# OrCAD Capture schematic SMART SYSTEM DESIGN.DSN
size A4; title: Smart System design; rev: H MB; company: University Of South Eastern Norway; note: Hugo MASSON-BENOIT; note: Hasbergs Vei 3
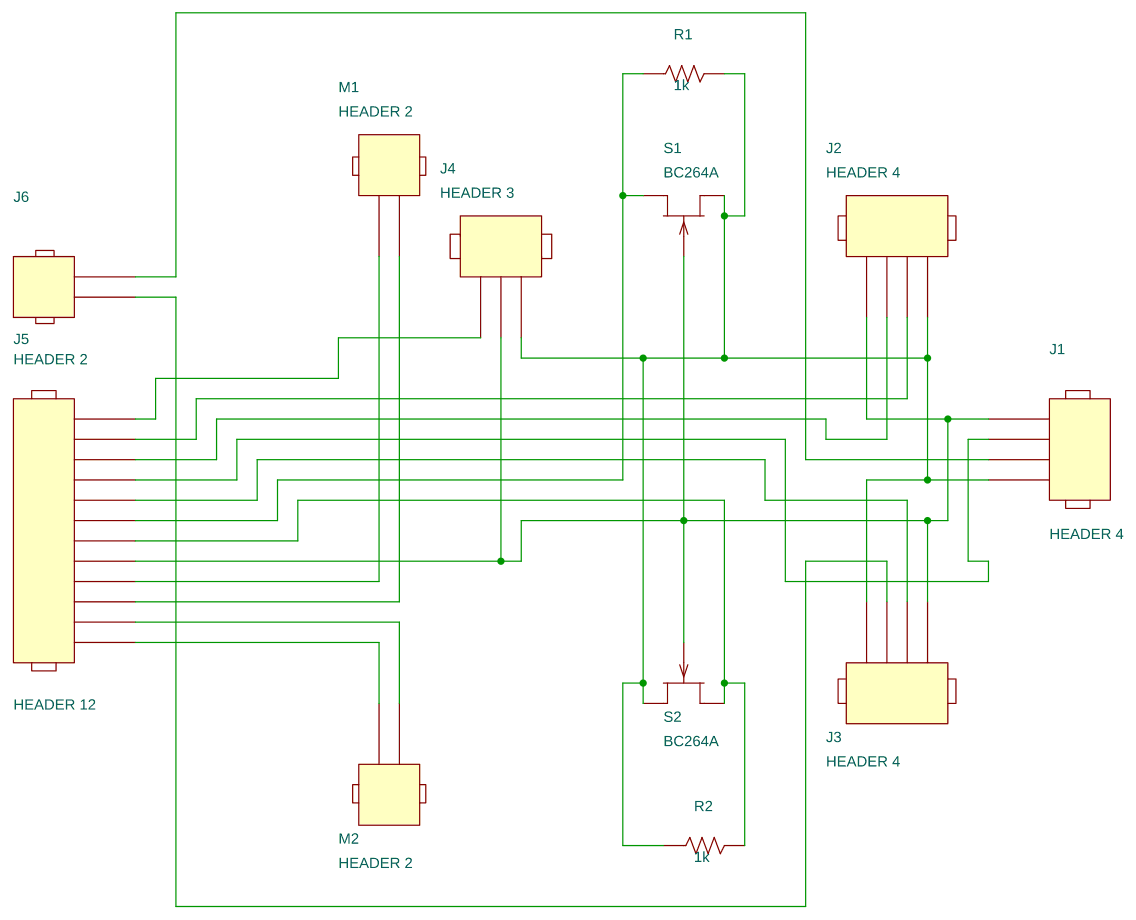
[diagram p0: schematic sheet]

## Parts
J1  HEADER 4  [SIPTML4004]
J2  HEADER 4  [SIPTML4004]
J3  HEADER 4  [SIPTML4004]
J4  HEADER 3  [SIPTML3003]
J5  HEADER 12  [SIPTML120012]
J6  HEADER 2  [SIPTML2002]
M1  HEADER 2  [SIPTML2002]
M2  HEADER 2  [SIPTML2002]
R1  1k  [AXRC05]
R2  1k  [AXRC05]
S1  BC264A  [TO92100]
S2  BC264A  [TO92100]

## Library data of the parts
J1-J3 = HEADER_4
J4 = HEADER_3
J5 = HEADER_12
J6 M1 M2 = HEADER_2
R1 R2 = R
S1 S2 = BC264A

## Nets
N00360: J4.3 J5.1
N00369: J1.4 J2.4 J3.4 J4.2 J5.8 S1.1(g) S2.1(g)
N00376: J1.1 J2.1 J3.1 J4.1 R1.2 R2.1 S1.2(s) S2.2(s)
N00451: J2.2 J5.2
N00455: J2.3 J5.3
N00470: J1.3 J5.4
N00474: J3.3 J5.5
N00833: J1.2 J6.1
N02519: J5.9 M1.2
N02528: J5.10 M1.1
N02537: J5.11 M2.2
N02546: J5.12 M2.1
N03250: J5.7 R2.2 S2.3(d)
N03273: J5.6 R1.1 S1.3(d)
N04280: J3.2 J6.2
